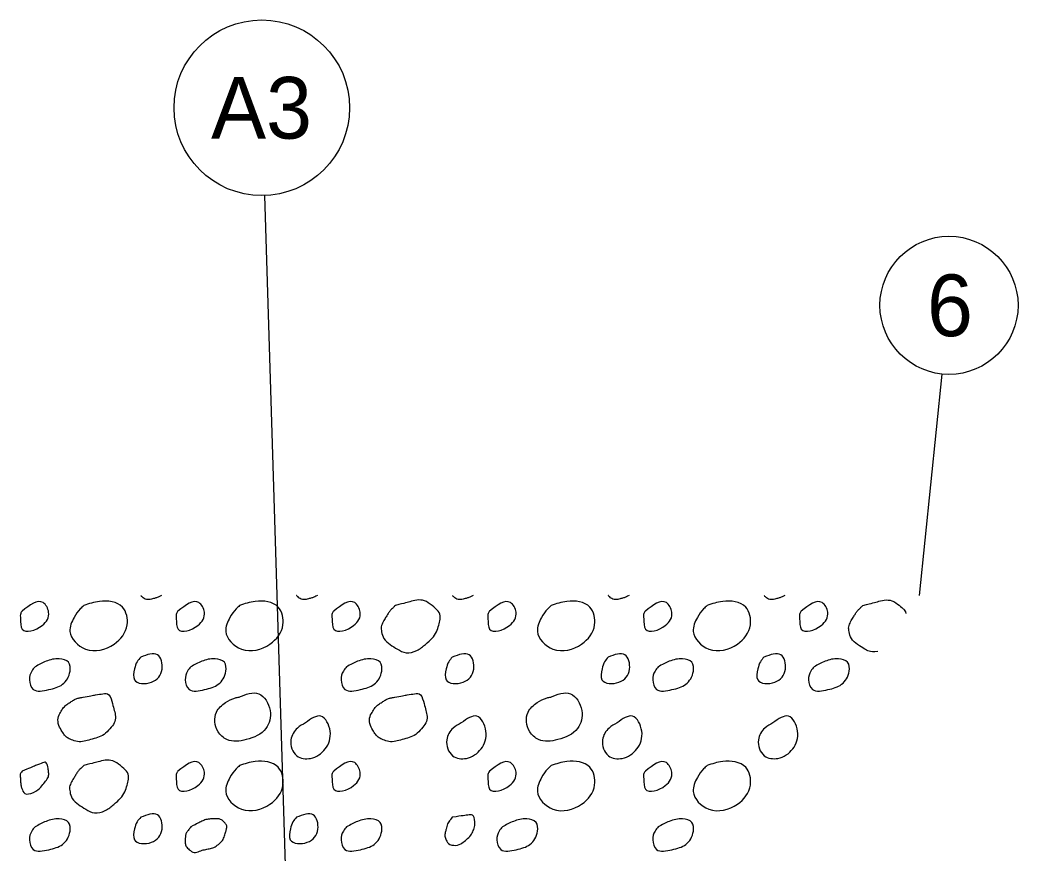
# Model space of a CAD drawing. Extents: x 0 to 340, y 0 to 220.
# Drawn here: x 150.51 to 173.16, y 163.56 to 182.46 of the extents above; entities that cross this region are included whole.
import ezdxf

# ---------------------------------------------------------------- set-up
doc = ezdxf.new("R2010")
doc.units = 0
for name, color, linetype in [('GE_P_Alignment_100_Stations', 7, 'Continuous'), ('MT_P_Work_Area', 7, 'Continuous'), ('SC_Scratch1', 7, 'Continuous')]:
    doc.layers.add(name, color=color, linetype=linetype)

msp = doc.modelspace()

# ---------------------------------------------------------------- linework, layer by layer
at = {"layer": 'GE_P_Alignment_100_Stations'}
for p, q in [((156.063, 178.476), (156.591, 161.331)), ((171.436, 174.427), (170.922, 169.406))]:
    msp.add_line(p, q, dxfattribs=at)
at = {"layer": 'MT_P_Work_Area'}
for centre, radius in [((156.002, 180.467), 1.992), ((171.595, 175.986), 1.567)]:
    msp.add_circle(centre, radius, dxfattribs=at)
at = {"layer": 'SC_Scratch1'}
for points in [[(150.563, 169.051), (151.038, 169.243), (151.164, 169.025), (151.015, 168.722), (150.565, 168.638), (150.525, 168.878), (150.53, 168.999), (150.563, 169.051)], [(151.962, 169.177), (152.318, 169.27), (152.839, 169.138), (152.946, 168.736), (152.65, 168.301), (152.002, 168.19), (151.648, 168.588), (151.743, 168.907), (151.881, 169.099), (151.962, 169.177)], [(154.099, 169.051), (154.574, 169.243), (154.699, 169.025), (154.55, 168.722), (154.1, 168.638), (154.061, 168.878), (154.065, 168.999), (154.099, 169.051)], [(155.498, 169.177), (155.854, 169.27), (156.374, 169.138), (156.482, 168.736), (156.186, 168.301), (155.538, 168.19), (155.184, 168.588), (155.279, 168.907), (155.417, 169.099), (155.498, 169.177)], [(157.634, 169.051), (158.109, 169.243), (158.235, 169.025), (158.086, 168.722), (157.636, 168.638), (157.597, 168.878), (157.601, 168.999), (157.634, 169.051)], [(161.17, 169.051), (161.645, 169.243), (161.771, 169.025), (161.622, 168.722), (161.172, 168.638), (161.133, 168.878), (161.137, 168.999), (161.17, 169.051)], [(162.569, 169.177), (162.925, 169.27), (163.446, 169.138), (163.554, 168.736), (163.258, 168.301), (162.609, 168.19), (162.255, 168.588), (162.35, 168.907), (162.489, 169.099), (162.569, 169.177)], [(164.706, 169.051), (165.181, 169.243), (165.307, 169.025), (165.158, 168.722), (164.708, 168.638), (164.669, 168.878), (164.673, 168.999), (164.706, 169.051)], [(166.105, 169.177), (166.461, 169.27), (166.982, 169.138), (167.089, 168.736), (166.794, 168.301), (166.145, 168.19), (165.791, 168.588), (165.886, 168.907), (166.024, 169.099), (166.105, 169.177)], [(168.242, 169.051), (168.717, 169.243), (168.843, 169.025), (168.694, 168.722), (168.244, 168.638), (168.204, 168.878), (168.209, 168.999), (168.242, 169.051)], [(153.253, 168.004), (153.635, 168.059), (153.739, 167.731), (153.499, 167.437), (153.112, 167.494), (153.115, 167.739), (153.173, 167.903), (153.253, 168.004)], [(160.324, 168.004), (160.706, 168.059), (160.81, 167.731), (160.57, 167.437), (160.184, 167.494), (160.186, 167.739), (160.244, 167.903), (160.324, 168.004)], [(163.86, 168.004), (164.242, 168.059), (164.346, 167.731), (164.106, 167.437), (163.719, 167.494), (163.722, 167.739), (163.78, 167.903), (163.86, 168.004)], [(167.396, 168.004), (167.778, 168.059), (167.882, 167.731), (167.642, 167.437), (167.255, 167.494), (167.258, 167.739), (167.316, 167.903), (167.396, 168.004)], [(150.855, 167.787), (151.105, 167.912), (151.405, 167.969), (151.616, 167.889), (151.65, 167.685), (151.48, 167.389), (151.166, 167.269), (150.815, 167.274), (150.729, 167.49), (150.78, 167.69), (150.855, 167.787)], [(154.39, 167.787), (154.64, 167.912), (154.941, 167.969), (155.152, 167.889), (155.186, 167.685), (155.015, 167.389), (154.702, 167.269), (154.35, 167.274), (154.264, 167.49), (154.316, 167.69), (154.39, 167.787)], [(157.926, 167.787), (158.176, 167.912), (158.477, 167.969), (158.688, 167.889), (158.722, 167.685), (158.551, 167.389), (158.238, 167.269), (157.886, 167.274), (157.8, 167.49), (157.852, 167.69), (157.926, 167.787)], [(164.998, 167.787), (165.248, 167.912), (165.549, 167.969), (165.759, 167.889), (165.794, 167.685), (165.623, 167.389), (165.309, 167.269), (164.958, 167.274), (164.872, 167.49), (164.924, 167.69), (164.998, 167.787)], [(168.534, 167.787), (168.784, 167.912), (169.084, 167.969), (169.295, 167.889), (169.329, 167.685), (169.159, 167.389), (168.845, 167.269), (168.494, 167.274), (168.408, 167.49), (168.459, 167.69), (168.534, 167.787)], [(155.477, 167.098), (155.931, 167.174), (156.19, 166.794), (156.094, 166.387), (155.648, 166.134), (155.208, 166.137), (155.009, 166.315), (154.972, 166.76), (155.177, 166.974), (155.403, 167.082), (155.485, 167.099)], [(162.549, 167.098), (163.003, 167.174), (163.262, 166.794), (163.165, 166.387), (162.719, 166.134), (162.279, 166.137), (162.08, 166.315), (162.044, 166.76), (162.249, 166.974), (162.474, 167.082), (162.557, 167.099)], [(156.993, 166.515), (157.344, 166.666), (157.552, 166.328), (157.44, 165.923), (157.107, 165.71), (156.796, 165.769), (156.663, 166.129), (156.809, 166.396), (156.993, 166.515)], [(160.529, 166.515), (160.88, 166.666), (161.088, 166.328), (160.976, 165.923), (160.643, 165.71), (160.332, 165.769), (160.199, 166.129), (160.344, 166.396), (160.529, 166.515)], [(164.064, 166.515), (164.416, 166.666), (164.624, 166.328), (164.512, 165.923), (164.179, 165.71), (163.868, 165.769), (163.734, 166.129), (163.88, 166.396), (164.064, 166.515)], [(167.6, 166.515), (167.952, 166.666), (168.159, 166.328), (168.048, 165.923), (167.714, 165.71), (167.404, 165.769), (167.27, 166.129), (167.416, 166.396), (167.6, 166.515)], [(154.099, 165.42), (154.574, 165.613), (154.699, 165.394), (154.55, 165.092), (154.1, 165.008), (154.061, 165.248), (154.065, 165.369), (154.099, 165.42)], [(155.498, 165.546), (155.854, 165.639), (156.374, 165.508), (156.482, 165.105), (156.186, 164.67), (155.538, 164.559), (155.184, 164.958), (155.279, 165.276), (155.417, 165.469), (155.498, 165.546)], [(157.634, 165.42), (158.109, 165.613), (158.235, 165.394), (158.086, 165.092), (157.636, 165.008), (157.597, 165.248), (157.601, 165.369), (157.634, 165.42)], [(161.17, 165.42), (161.645, 165.613), (161.771, 165.394), (161.622, 165.092), (161.172, 165.008), (161.133, 165.248), (161.137, 165.369), (161.17, 165.42)], [(162.569, 165.546), (162.925, 165.639), (163.446, 165.508), (163.554, 165.105), (163.258, 164.67), (162.609, 164.559), (162.255, 164.958), (162.35, 165.276), (162.489, 165.469), (162.569, 165.546)], [(164.706, 165.42), (165.181, 165.613), (165.307, 165.394), (165.158, 165.092), (164.708, 165.008), (164.669, 165.248), (164.673, 165.369), (164.706, 165.42)], [(166.105, 165.546), (166.461, 165.639), (166.982, 165.508), (167.089, 165.105), (166.794, 164.67), (166.145, 164.559), (165.791, 164.958), (165.886, 165.276), (166.024, 165.469), (166.105, 165.546)], [(153.253, 164.373), (153.635, 164.429), (153.739, 164.101), (153.499, 163.806), (153.112, 163.863), (153.115, 164.109), (153.173, 164.272), (153.253, 164.373)], [(156.789, 164.373), (157.17, 164.429), (157.274, 164.101), (157.034, 163.806), (156.648, 163.863), (156.65, 164.109), (156.709, 164.272), (156.789, 164.373)], [(150.855, 164.156), (151.105, 164.281), (151.405, 164.339), (151.616, 164.258), (151.65, 164.055), (151.48, 163.758), (151.166, 163.638), (150.815, 163.644), (150.729, 163.86), (150.78, 164.06), (150.855, 164.156)], [(157.926, 164.156), (158.176, 164.281), (158.477, 164.339), (158.688, 164.258), (158.722, 164.055), (158.551, 163.758), (158.238, 163.638), (157.886, 163.644), (157.8, 163.86), (157.852, 164.06), (157.926, 164.156)], [(161.462, 164.156), (161.712, 164.281), (162.013, 164.339), (162.224, 164.258), (162.258, 164.055), (162.087, 163.758), (161.774, 163.638), (161.422, 163.644), (161.336, 163.86), (161.388, 164.06), (161.462, 164.156)], [(164.998, 164.156), (165.248, 164.281), (165.549, 164.339), (165.759, 164.258), (165.794, 164.055), (165.623, 163.758), (165.309, 163.638), (164.958, 163.644), (164.872, 163.86), (164.924, 164.06), (164.998, 164.156)]]:
    msp.add_spline(points, degree=3, dxfattribs=at)
for points in [[(153.728, 169.406), (153.678, 169.378), (153.625, 169.357), (153.571, 169.341), (153.475, 169.312), (153.354, 169.307), (153.26, 169.4), (153.258, 169.402), (153.256, 169.404), (153.254, 169.406)], [(157.264, 169.406), (157.214, 169.378), (157.161, 169.357), (157.107, 169.341), (157.011, 169.312), (156.89, 169.307), (156.796, 169.4), (156.794, 169.402), (156.792, 169.404), (156.79, 169.406)], [(159.034, 169.177), (159.152, 169.208), (159.271, 169.239), (159.389, 169.27), (159.563, 169.315), (159.737, 169.283), (159.91, 169.138), (160.045, 169.026), (160.053, 168.86), (160.018, 168.736), (159.973, 168.579), (159.874, 168.431), (159.722, 168.301), (159.532, 168.139), (159.268, 168.075), (159.074, 168.19), (158.916, 168.283), (158.75, 168.423), (158.719, 168.588), (158.701, 168.691), (158.754, 168.811), (158.814, 168.907), (158.858, 168.975), (158.896, 169.044), (158.953, 169.099), (158.98, 169.125), (159.007, 169.151), (159.034, 169.177)], [(160.8, 169.406), (160.749, 169.378), (160.697, 169.357), (160.643, 169.341), (160.547, 169.312), (160.426, 169.307), (160.332, 169.4), (160.33, 169.402), (160.328, 169.404), (160.326, 169.406)], [(164.336, 169.406), (164.285, 169.378), (164.233, 169.357), (164.179, 169.341), (164.083, 169.312), (163.962, 169.307), (163.868, 169.4), (163.866, 169.402), (163.864, 169.404), (163.862, 169.406)], [(167.872, 169.406), (167.821, 169.378), (167.768, 169.357), (167.714, 169.341), (167.619, 169.312), (167.498, 169.307), (167.404, 169.4), (167.402, 169.402), (167.4, 169.404), (167.398, 169.406)], [(169.641, 169.177), (169.76, 169.208), (169.878, 169.239), (169.997, 169.27), (170.17, 169.315), (170.345, 169.283), (170.518, 169.138), (170.567, 169.097), (170.6, 169.048), (170.619, 168.997)], [(169.983, 168.137), (169.877, 168.122), (169.772, 168.136), (169.681, 168.19), (169.524, 168.283), (169.357, 168.423), (169.327, 168.588), (169.308, 168.691), (169.362, 168.811), (169.422, 168.907), (169.465, 168.975), (169.503, 169.044), (169.56, 169.099), (169.587, 169.125), (169.614, 169.151), (169.641, 169.177)], [(151.941, 167.098), (152.092, 167.124), (152.244, 167.153), (152.395, 167.174), (152.547, 167.195), (152.617, 166.935), (152.655, 166.794), (152.689, 166.665), (152.667, 166.507), (152.558, 166.387), (152.425, 166.239), (152.276, 166.183), (152.112, 166.134), (151.971, 166.093), (151.813, 166.078), (151.672, 166.137), (151.587, 166.173), (151.525, 166.235), (151.473, 166.315), (151.386, 166.449), (151.361, 166.634), (151.436, 166.76), (151.486, 166.844), (151.554, 166.918), (151.641, 166.974), (151.715, 167.021), (151.785, 167.065), (151.867, 167.082), (151.895, 167.088), (151.922, 167.094), (151.95, 167.099)], [(159.013, 167.098), (159.164, 167.124), (159.316, 167.153), (159.467, 167.174), (159.618, 167.195), (159.688, 166.935), (159.726, 166.794), (159.761, 166.665), (159.738, 166.507), (159.629, 166.387), (159.496, 166.239), (159.348, 166.183), (159.184, 166.134), (159.042, 166.093), (158.884, 166.078), (158.744, 166.137), (158.658, 166.173), (158.596, 166.235), (158.544, 166.315), (158.458, 166.449), (158.432, 166.634), (158.508, 166.76), (158.558, 166.844), (158.626, 166.918), (158.713, 166.974), (158.787, 167.021), (158.857, 167.065), (158.939, 167.082), (158.966, 167.088), (158.994, 167.094), (159.021, 167.099)], [(150.563, 165.42), (150.721, 165.484), (150.88, 165.552), (151.038, 165.613), (151.116, 165.642), (151.157, 165.469), (151.164, 165.394), (151.173, 165.295), (151.097, 165.191), (151.015, 165.092), (150.903, 164.958), (150.622, 164.86), (150.565, 165.008), (150.534, 165.086), (150.529, 165.167), (150.525, 165.248), (150.524, 165.288), (150.509, 165.333), (150.53, 165.369), (150.54, 165.387), (150.552, 165.403), (150.563, 165.42)], [(151.962, 165.546), (152.081, 165.578), (152.199, 165.609), (152.318, 165.639), (152.491, 165.684), (152.665, 165.653), (152.839, 165.508), (152.973, 165.395), (152.982, 165.229), (152.946, 165.105), (152.901, 164.949), (152.802, 164.8), (152.65, 164.67), (152.46, 164.508), (152.196, 164.444), (152.002, 164.559), (151.844, 164.653), (151.678, 164.793), (151.648, 164.958), (151.629, 165.061), (151.682, 165.18), (151.743, 165.276), (151.786, 165.344), (151.824, 165.414), (151.881, 165.469), (151.908, 165.495), (151.935, 165.52), (151.962, 165.546)], [(160.324, 164.373), (160.452, 164.392), (160.579, 164.412), (160.706, 164.429), (160.82, 164.444), (160.846, 164.199), (160.81, 164.101), (160.771, 163.992), (160.672, 163.884), (160.57, 163.806), (160.465, 163.726), (160.244, 163.74), (160.184, 163.863), (160.145, 163.941), (160.165, 164.031), (160.186, 164.109), (160.201, 164.164), (160.209, 164.227), (160.244, 164.272), (160.271, 164.306), (160.298, 164.34), (160.324, 164.373)], [(154.39, 164.156), (154.474, 164.198), (154.557, 164.24), (154.64, 164.281), (154.732, 164.327), (154.841, 164.336), (154.941, 164.339), (155.015, 164.341), (155.086, 164.324), (155.152, 164.258), (155.213, 164.198), (155.204, 164.118), (155.186, 164.055), (155.157, 163.95), (155.117, 163.843), (155.015, 163.758), (154.915, 163.675), (154.809, 163.663), (154.702, 163.638), (154.589, 163.612), (154.46, 163.545), (154.35, 163.644), (154.278, 163.709), (154.263, 163.785), (154.264, 163.86), (154.266, 163.926), (154.274, 164.004), (154.316, 164.06), (154.341, 164.092), (154.365, 164.124), (154.39, 164.156)]]:
    msp.add_open_spline(points, degree=3, dxfattribs=at)

# ---------------------------------------------------------------- texts
at = {"layer": 'MT_P_Work_Area'}
for s, p in [('A3', (154.85, 179.767)), ('6', (171.096, 175.286))]:
    msp.add_text(s, height=1.4, dxfattribs=at).set_placement(p)

doc.saveas('drawing.dxf')
